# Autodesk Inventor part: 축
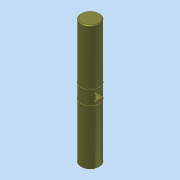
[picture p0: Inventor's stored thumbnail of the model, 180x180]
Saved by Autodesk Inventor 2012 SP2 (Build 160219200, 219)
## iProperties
Company: 한국ATC센터
Created: 2015-04
Part Number: 축
Document SubType Name: Modeling
Designer: KYOUNG IL JANG
Density: 7.85 g/cm^3
Material: 강
Author: KYOUNG IL JANG
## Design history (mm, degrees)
sketch "스케치1"
  geometry: C1 r 11 at (0, 0); 1 further point
  constraints: 1 centre point, 1 coincident
  dimensions: "d0" = 22 diameter of C1
extrude "돌출1" new body sketch "스케치1" stored distance "d1" = 150; taper "d2" = 0 deg
sketch "스케치2"
  geometry: L1 (-10.247, -4)-(10.247, -4); L2 (-10.247, 4)-(10.247, 4); A1 r 11 centre (0, 0) between (-10.247, -4) and (10.247, -4) reference; 1 further point
  constraints: 4 end point, 4 point on circle, 2 parallel, 1 horizontal
  dimensions: "d3" = 8 distance between parallel lines of L2 L1
extrude "돌출2" cut sketch "스케치2" stored distance "d4" = 8; taper "d5" = 0 deg
sketch "스케치3"
  geometry: 5 further points
hole "구멍1" sketch "스케치3" at (-4, 4), (4, 4), (4, -4), (-4, -4) diameter "d6" = 2; stored, may be unused: countersink angle "d10" = 90 deg, drill point angle "d12" = 118 deg; dims "d7" = 6, "d8" = 4, "d9" = 2, "d11" = 8
chamfer "모따기1" distance "d13" = 1; stored, may be unused: second distance "d14" = 2, angle "d15" = 45 deg
sketch "스케치4"
  geometry: L1 (-10, 9)-(-11, 9); L2 (-11, 9)-(-11, 7.8); L3 (-11, 7.8)-(-10, 7.8); L4 (-10, 7.8)-(-10, 9); L5 (-10, 75)-(10, 75) reference; L6 (0, -10)-(0, 60) reference; 1 further point
  constraints: 8 end point, 2 parallel, 1 horizontal, 1 perpendicular
  dimensions: "d16" = 7.8 distance from line of L3 point (0, 0); "d17" = 67.2 distance between parallel lines of L3 L5 (derived); "d18" = 11 distance from line of point (0, 0) L2; "d19" = 1 distance of L2.end L3.end; "d20" = 1.2 distance of L1.end L2.end
revolve "회전1" sketch "스케치4" stored, may be unused: angle "d21" = 90 deg
node "솔리드1"
mirror "대칭1"
mirror "대칭2"
